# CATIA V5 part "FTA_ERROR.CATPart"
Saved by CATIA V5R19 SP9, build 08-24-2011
Part number: PART1
Property "3DZP_INDEX_TXT": 2
Bounding box of the stored display mesh (mm): x 0 to 974.413, y -60.374 to 60.374, z 0 to 156.2
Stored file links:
  D:\USERS\ehenry3\TestDaten\FTA_ERROR.CATPart
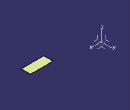
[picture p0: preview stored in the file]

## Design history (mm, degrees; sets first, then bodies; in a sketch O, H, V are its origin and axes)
AxisSystem1: origin (0, 0, 0), X (1, 0, 0), Y (0, 1, 0), Z (0, 0, 1)
TTRSSet1
f4a2d38f3ddc11d3a929006094b99c4b_11 "CATTPSSet"
Set1
  DatumCurve1
  Fill1: Boundary DatumCurve1
Body1 (main body)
